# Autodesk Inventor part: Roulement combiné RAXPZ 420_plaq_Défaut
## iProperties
Shininess: 64.0
Length Units: 11269
Angle Units: 11279
Time Units: 11290
Mass Units: 11283
Length Display Precision: 3
Angle Display Precision: 2
Compacted: True
Part Number: Roulement combiné RAXPZ 420_plaq_Défaut
Document SubType Name: Modeling
Created: 2006-01
Material: Par défaut
Designer: riri
Density: 0.0
Volumn: 0.0
Area: 0.0
PropertySet Name: Model Information
Control State: 0
Master: False
Checked Out: False
Author: riri
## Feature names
1. Base1
